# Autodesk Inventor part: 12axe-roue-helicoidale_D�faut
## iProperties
Created: 2011-01
Part Number: 12axe-roue-helicoidale_D�faut
Document SubType Name: Modeling
Designer: eric
Density: 1 g/cm^3
Mass: 8.20486 g
Surface Area: 66.231 cm^2
Volume: 8.20486 cm^3
Author: eric
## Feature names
1. Base1
